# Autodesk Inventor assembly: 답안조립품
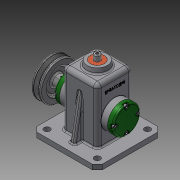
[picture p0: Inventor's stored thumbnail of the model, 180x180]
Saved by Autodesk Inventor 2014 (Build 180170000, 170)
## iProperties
Created: 2016-02
Part Number: 답안조립품
Document SubType Name: Assembly
Designer: Administrator
Author: Administrator
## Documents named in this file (16)
- C:\Users\Administrator\Desktop\460211V1028\답안조립품.iam
- C:\Users\Administrator\Desktop\460211V1028\1-본체.ipt
- C:\Users\Administrator\Desktop\460211V1028\V벨트풀리.ipt
- C:\Users\Administrator\Desktop\460211V1028\고정핀 1.2 x 10.ipt
- C:\Users\Administrator\Desktop\460211V1028\뒤커버.ipt
- C:\Users\Administrator\Desktop\460211V1028\링크.ipt
- C:\Users\Administrator\Desktop\460211V1028\멈춤나사 M3x8.ipt
- C:\Users\Administrator\Desktop\460211V1028\베어링 12 x 32 x 10.ipt
- C:\Users\Administrator\Desktop\460211V1028\볼트 M4 x 12.ipt
- C:\Users\Administrator\Desktop\460211V1028\부시.ipt
- C:\Users\Administrator\Desktop\460211V1028\슬라이드.ipt
- C:\Users\Administrator\Desktop\460211V1028\앞커버.ipt
- C:\Users\Administrator\Desktop\460211V1028\오일실 12 25 7.ipt
- C:\Users\Administrator\Desktop\460211V1028\키 4 x 4 x 10.ipt
- C:\Users\Administrator\Desktop\460211V1028\편심축.ipt
- C:\Users\Administrator\Desktop\460211V1028\핀 5 x 18.ipt
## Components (12 placed, 5 different names)
1. 1-본체:1 — 각도:4, 각도:5
2. V벨트풀리:1 — 플러쉬:2
3. 고정핀 1.2 x 10:1 — 각도:1, 각도:2, 각도:3
4. 핀 5 x 18:1
5. ISO 4762 M4 x 12:1 — 각도:4
6. ISO 4762 M4 x 12:3
7. ISO 4762 M4 x 12:4
8. ISO 4762 M4 x 12:5
9. ISO 4762 M4 x 12:2 — 각도:5
10. ISO 4762 M4 x 12:6
11. ISO 4762 M4 x 12:7
12. ISO 4762 M4 x 12:8
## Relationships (6: Angle 5, Flush 1)
- 각도:1 [Angle]: 고정핀 1.2 x 10:1
- 각도:2 [Angle]: 고정핀 1.2 x 10:1
- 각도:3 [Angle]: 고정핀 1.2 x 10:1
- 각도:4 [Angle]: 1-본체:1 ↔ ISO 4762 M4 x 12:1
- 각도:5 [Angle]: 1-본체:1 ↔ ISO 4762 M4 x 12:2
- 플러쉬:2 [Flush]: V벨트풀리:1
